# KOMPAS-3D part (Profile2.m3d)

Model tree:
1. Plane XY
2. Plane ZX
3. Plane ZY
4. X Axis
5. Y Axis
6. Z Axis
7. Origin
8. Sketch:1
9. Extrude:1
     Wall Thickness 1 = 1; Wall Thickness 2 = 1; Distance 1 = 2000; Distance 2 = 10
10. Sketch:2
11. Extrude:2
     Wall Thickness 1 = 1; Wall Thickness 2 = 1; Distance 1 = 190; Distance 2 = 10
12. Three Point Plane:1
13. Sketch:3
14. Extrude:3
     Wall Thickness 1 = 1; Wall Thickness 2 = 1; Distance 1 = 190; Distance 2 = 10

Referenced files in D:\Documents and Settings\kashirsky\Рабочий стол\Seminar\: Cottage_balcony.a3d
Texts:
  Steel DIN 17102
  Three Point Plane
  Plane at Angle
  Line and Point Plane
  Axis through Two Vertices
  Axis of Feature
  Axis of Conical Surface
  Axis through Edge
  Trim by Surface
  Trim by Sketch
  Feature with No History
  Intersection Axis of Two Planes
  Two Line Plane
  Line and Face Plane
  Bend by line
  Hole in sheet body
  Cut in sheet body
  Point in CM
  Linear Dimension from Line to Point
  Surface Finish Symbol
  Geometric Tolerance Symbol
  Leader #1
  Leader #2
  Leader #3
  Shape Deviations and Datum
  Node point number
  Mark of coordination axis
  Node point designation
  Mark/Reference designation with leader
  Mark/reference designation on line
  Mark/Reference designation without leader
